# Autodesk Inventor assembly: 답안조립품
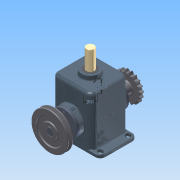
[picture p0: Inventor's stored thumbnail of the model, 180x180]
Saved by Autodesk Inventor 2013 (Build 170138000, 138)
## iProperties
Created: 2015-03
Part Number: 답안조립품
Document SubType Name: Assembly
Designer: Administrator
Mass: 8579.28 g
Surface Area: 4386.42 cm^2
Volume: 1982.54 cm^3
Density: 4.32742 g/cm^3
Author: Administrator
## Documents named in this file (15)
- C:\Documents and Settings\Administrator\바탕 화면\350305V1018\답안조립품.iam
- C:\Documents and Settings\Administrator\바탕 화면\350305V1018\본체.ipt
- C:\Documents and Settings\Administrator\바탕 화면\350305V1018\베어링 6205.ipt
- C:\Documents and Settings\Administrator\바탕 화면\350305V1018\커버.ipt
- C:\Documents and Settings\Administrator\바탕 화면\350305V1018\편심축.ipt
- C:\Documents and Settings\Administrator\바탕 화면\350305V1018\오일실.ipt
- C:\Documents and Settings\Administrator\바탕 화면\350305V1018\멈춤링.ipt
- C:\Documents and Settings\Administrator\바탕 화면\350305V1018\키 8x8.ipt
- C:\Documents and Settings\Administrator\바탕 화면\350305V1018\체인 스프로킷.ipt
- C:\Documents and Settings\Administrator\바탕 화면\350305V1018\V-벨트풀리.ipt
- C:\Documents and Settings\Administrator\바탕 화면\350305V1018\M4x0.5.ipt
- C:\Documents and Settings\Administrator\바탕 화면\350305V1018\멈춤나사 M5x0.5.ipt
- C:\Documents and Settings\Administrator\바탕 화면\350305V1018\부시.ipt
- C:\Documents and Settings\Administrator\바탕 화면\350305V1018\슬라이드.ipt
- C:\Documents and Settings\Administrator\바탕 화면\350305V1018\가변스프링.ipt
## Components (9 placed, 4 different names)
1. 5-체인 스프로킷:1 — 플러쉬:1, 각도:3
2. V-벨트풀리:1 — 플러쉬:2, 각도:4
3. M4x0.5:1
4. M4x0.5:2
5. M4x0.5:3
6. M4x0.5:4
7. M4x0.5:5
8. M4x0.5:6
9. 가변스프링:1
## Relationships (4: Flush 2, Angle 2)
- 플러쉬:1 [Flush]: 5-체인 스프로킷:1
- 각도:3 [Angle]: 5-체인 스프로킷:1
- 플러쉬:2 [Flush]: V-벨트풀리:1
- 각도:4 [Angle]: V-벨트풀리:1
